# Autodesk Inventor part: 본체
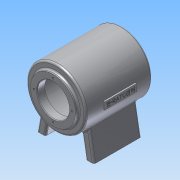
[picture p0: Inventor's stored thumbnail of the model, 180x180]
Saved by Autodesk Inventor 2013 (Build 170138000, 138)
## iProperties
Created: 2015-01
Part Number: 본체
Material: 알루미늄 6061
Document SubType Name: Modeling
Designer: Administrator
Density: 2.71 g/cm^3
Mass: 1021.13 g
Surface Area: 1060.37 cm^2
Volume: 376.8 cm^3
Author: Administrator
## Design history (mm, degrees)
sketch "스케치1"
  geometry: C1 r 50 at (0, 0); 1 further point
  constraints: 1 centre point, 1 coincident
  dimensions: "d0" = 100 diameter of C1
extrude "돌출1" new body sketch "스케치1" stored distance "d1" = 112; taper "d2" = 0 deg
sketch "스케치2"
  geometry: C1 r 50 at (0, 0) reference; C2 r 38 at (0, 0)
  constraints: 1 centre point, 1 coincident
  dimensions: "d3" = 76 diameter of C2
extrude "돌출2" join sketch "스케치2" distance "d4" = 5; taper "d5" = 0 deg
sketch "스케치3"
  geometry: C1 r 50 at (0, 0) reference; C2 r 38 at (0, 0)
  constraints: 1 centre point, 1 coincident
  dimensions: "d6" = 76 diameter of C2
extrude "돌출3" join sketch "스케치3" distance "d7" = 5; taper "d8" = 0 deg
sketch "스케치5"
  geometry: C1 r 38 at (0, 0) reference; C2 r 27 at (0, 0)
  constraints: 1 centre point, 1 coincident
  dimensions: "d12" = 54 diameter of C2
extrude "돌출5" cut sketch "스케치5" stored distance "d13" = 97; taper "d14" = 0 deg
sketch "스케치6"
  geometry: C1 r 27 at (0, 0) reference; 1 further point
  constraints: 1 vertical alignment
  dimensions: "d15" = 32 distance of C1.centre point (0, 32)
hole "구멍1" sketch "스케치6" at (0, 32) diameter "d16" = 3.242; stored, may be unused: countersink angle "d20" = 90 deg, drill point angle "d22" = 118 deg; dims "d17" = 8, "d18" = 4, "d19" = 2, "d21" = 10
sketch "스케치7"
  geometry: L1 (-48, -80)-(-34, -80); L2 (-39.336, -30.865)-(-48, -80); L3 (-34, -80)-(-27.282, -41.901); C1 r 38 at (0, 0) reference; A1 r 50 centre (0, 0) between (-39.336, -30.865) and (-27.282, -41.901) reference; A2 r 50 centre (0, 0) between (-39.336, -30.865) and (-27.282, -41.901) reference; 1 further point
  constraints: 6 end point, 4 point on circle, 1 horizontal
  dimensions: "d26" = 80 distance from line of point (0, 0) L1; "d28" = 80 deg angle of L1 L3; "d29" = 100 deg angle of L1 L2; "d30" = 14 distance of L1.end L1.start; "d31" = 48 horizontal distance of point (0, 0) L1.start
feature "리브1" sketch "스케치7" dims "d32" = 1, "d33" = 80, "d34" = 0, "d35" = 0, "d36" = 1, "d37" = 1
node "작업 평면1"
node "작업 평면5"
  node "작업 평면4"
sketch "스케치13"
  geometry: L1 (6, 26)-(-6, 26); L2 (-6, 26)-(-6, -28); L3 (-6, -28)-(6, -28); L4 (6, -28)-(6, 26); L5 (62, 37)-(62, -39) reference; L6 (38, 61)-(-38, 61) reference; 2 further points
  constraints: 8 end point, 2 parallel, 1 horizontal, 1 midpoint, 1 perpendicular, 1 vertical alignment
  dimensions: "d75" = 54 distance of L3.end L1.start; "d77" = 12 distance of L1.start L1.end; "d78" = 35 distance between parallel lines of L1 L6
extrude "돌출9" join sketch "스케치13" stored distance "d79" = 97; taper "d80" = 0 deg
sketch "스케치14"
  geometry: L1 (-61, 38)-(-61, -38) reference; 2 further points
  constraints: 1 horizontal alignment, 1 other
  dimensions: "d81" = 62 distance from line of L1 point (1, 0)
feature "엠보싱1" sketch "스케치14" dims "d82" = 0.5, "d83" = 0
fillet "모깎기1" dims "d101" = 3
fillet "모깎기2" dims "d102" = 3
chamfer "모따기1" distance "d103" = 1; stored, may be unused: second distance "d104" = 2, angle "d105" = 45 deg
node "작업 평면6"
sketch "스케치18"
  geometry: C1 r 50 at (0, 0) reference; C2 r 45 at (0, 0); 1 further point
  constraints: 1 centre point, 1 coincident
  dimensions: "d107" = 90 diameter of C2
extrude "돌출12" cut sketch "스케치18" distance "d108" = 49; taper "d109" = 0 deg; dims "d110" = 48, "d111" = 0
node "솔리드1"
pattern_circular "원형 패턴1" dims angle "d24" = 360 deg
mirror "대칭1"
mirror "대칭2"
node "투영된 루프2"
other parameters: "d38" = 62, "d74" = 2, "d106" = -62
